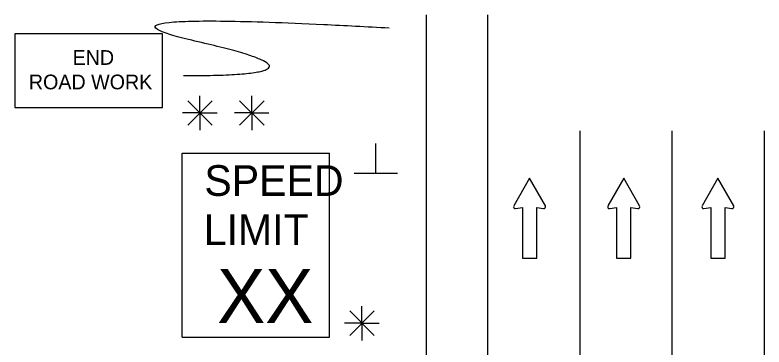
# Model space of a CAD drawing. Extents: x 16730 to 18479, y 5752 to 6927.
# Drawn here: x 16772.6 to 16967.7, y 6840.1 to 6926.7 of the extents above; entities that cross this region are included whole.
import ezdxf

# ---------------------------------------------------------------- set-up
doc = ezdxf.new("R2010")
doc.units = 0
for name, color, linetype in [('ALI_LEGAL_EX', 7, 'Continuous'), ('MT_SCRATCH_LEVEL_E', 7, 'Continuous'), ('PAVT_EDGE_EX', 7, 'Continuous'), ('TRAFFIC_SIGNS_PR', 7, 'Continuous'), ('TYPICAL_TEXT_DIMEN_PR', 7, 'Continuous')]:
    doc.layers.add(name, color=color, linetype=linetype)

msp = doc.modelspace()

# ---------------------------------------------------------------- linework, layer by layer
at = {"layer": 'ALI_LEGAL_EX'}
for p, q in [((16919.74, 6876.43), (16919.74, 5996.39)), ((16943.74, 6876.43), (16943.74, 5996.39)), ((16967.74, 6876.43), (16967.74, 5996.39))]:
    msp.add_line(p, q, dxfattribs=at)
for points in [[(16919.74, 6896.46), (16919.74, 6871.46)], [(16943.74, 6896.46), (16943.74, 6871.46)], [(16967.74, 6896.46), (16967.74, 6871.46)]]:
    msp.add_lwpolyline(points, dxfattribs=at)
at = {"layer": 'MT_SCRATCH_LEVEL_E'}
for p, q in [((16906.65, 6884.13), (16902.54, 6876.89)), ((16910.79, 6876.89), (16906.65, 6884.13)), ((16931.18, 6884.13), (16927.06, 6876.89)), ((16935.32, 6876.89), (16931.18, 6884.13)), ((16955.7, 6884.13), (16951.59, 6876.89)), ((16959.85, 6876.89), (16955.7, 6884.13)), ((16903.02, 6876.2), (16904.79, 6876.52)), ((16904.79, 6876.52), (16904.79, 6863.26)), ((16908.54, 6863.26), (16908.54, 6876.52)), ((16908.54, 6876.52), (16910.31, 6876.2)), ((16927.55, 6876.2), (16929.32, 6876.52)), ((16929.32, 6876.52), (16929.32, 6863.26)), ((16933.07, 6863.26), (16933.07, 6876.52)), ((16933.07, 6876.52), (16934.84, 6876.2)), ((16952.08, 6876.2), (16953.85, 6876.52)), ((16953.85, 6876.52), (16953.85, 6863.26)), ((16957.59, 6863.26), (16957.59, 6876.52)), ((16957.59, 6876.52), (16959.37, 6876.2)), ((16904.79, 6863.26), (16908.54, 6863.26)), ((16929.32, 6863.26), (16933.07, 6863.26)), ((16953.85, 6863.26), (16957.59, 6863.26))]:
    msp.add_line(p, q, dxfattribs=at)
for centre, start, end in [((16902.94, 6876.66), 150.4248, 279.9638), ((16910.38, 6876.66), 260.0362, 29.7731), ((16927.47, 6876.66), 150.4248, 279.9638), ((16934.91, 6876.66), 260.0362, 29.7731), ((16952, 6876.66), 150.4248, 279.9638), ((16959.44, 6876.66), 260.0362, 29.7731)]:
    msp.add_arc(centre, 0.463, start, end, dxfattribs=at)
at = {"layer": 'PAVT_EDGE_EX'}
for p, q in [((16879.74, 6926.69), (16879.74, 6016.42)), ((16895.74, 6926.69), (16895.74, 6016.42))]:
    msp.add_line(p, q, dxfattribs=at)
at = {"layer": 'TRAFFIC_SIGNS_PR'}
for p, q in [((16816.17, 6890.66), (16854.57, 6890.66)), ((16816.17, 6842.66), (16816.17, 6890.66)), ((16854.57, 6842.66), (16854.57, 6890.66)), ((16816.17, 6842.66), (16854.57, 6842.66))]:
    msp.add_line(p, q, dxfattribs=at)
msp.add_lwpolyline([(16772.61, 6902.56), (16811.01, 6902.56), (16811.01, 6921.76), (16772.61, 6921.76)], close=True, dxfattribs=at)
msp.add_open_spline([(16816.53, 6910.87), (16859.04, 6910.87), (16782.52, 6928.28), (16870.07, 6923.34)], degree=2, dxfattribs=at)
at = {"layer": 'TYPICAL_TEXT_DIMEN_PR'}
for p, q in [((16820.79, 6901.14), (16820.79, 6905.59)), ((16834.29, 6901.14), (16834.29, 6905.59)), ((16817.6, 6904.32), (16823.97, 6897.95)), ((16823.97, 6904.32), (16817.6, 6897.95)), ((16837.48, 6904.32), (16831.1, 6897.95)), ((16831.11, 6904.32), (16837.48, 6897.95)), ((16820.79, 6901.14), (16816.25, 6901.14)), ((16820.79, 6901.14), (16823.97, 6901.14)), ((16820.79, 6901.14), (16825.26, 6901.14)), ((16820.79, 6901.14), (16820.79, 6896.64)), ((16834.29, 6901.14), (16829.76, 6901.14)), ((16834.29, 6901.14), (16837.48, 6901.14)), ((16834.29, 6901.14), (16838.77, 6901.14)), ((16834.29, 6901.14), (16834.29, 6896.64)), ((16866.61, 6885.41), (16866.61, 6893.19)), ((16860.99, 6885.41), (16872.24, 6885.41)), ((16859.82, 6849.54), (16866.19, 6843.16)), ((16866.19, 6849.54), (16859.82, 6843.16)), ((16863, 6846.35), (16863, 6850.81)), ((16863, 6846.35), (16858.47, 6846.35)), ((16863, 6846.35), (16866.19, 6846.35)), ((16863, 6846.35), (16867.48, 6846.35)), ((16863, 6846.35), (16863, 6841.85))]:
    msp.add_line(p, q, dxfattribs=at)

# ---------------------------------------------------------------- texts
at = {"layer": 'TRAFFIC_SIGNS_PR'}
for s, height, p in [('END', 3.831, (16787.61, 6913.69)), ('ROAD WORK', 3.831, (16776.22, 6907.31)), ('SPEED', 8, (16821.94, 6879.53)), ('LIMIT', 8, (16821.78, 6866.73)), ('XX', 14.031, (16825.29, 6846.42))]:
    msp.add_text(s, height=height, dxfattribs=at).set_placement(p)

doc.saveas('drawing.dxf')
